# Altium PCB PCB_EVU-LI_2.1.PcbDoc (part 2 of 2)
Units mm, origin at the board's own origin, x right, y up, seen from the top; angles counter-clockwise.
Board outline 33.02 x 17.78 mm, 4 copper layers (Top, Int_1, Int_2, Bot), stack 1.546 mm thick; 75 components, 60 nets, 297 pads, 132 vias.
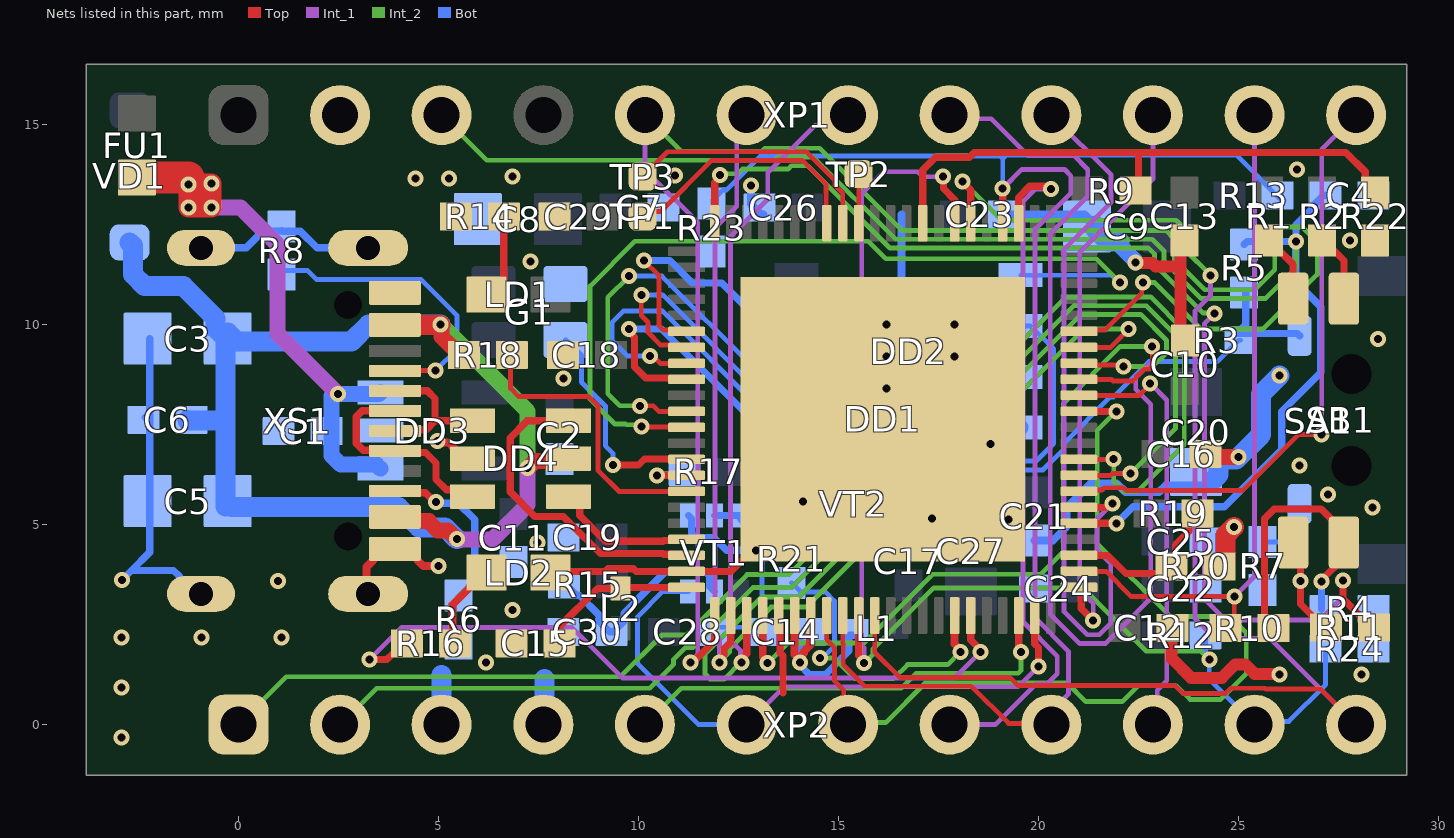
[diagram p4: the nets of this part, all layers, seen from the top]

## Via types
v1: diameter 0.4, hole 0.2, Top to Bot, 132 vias

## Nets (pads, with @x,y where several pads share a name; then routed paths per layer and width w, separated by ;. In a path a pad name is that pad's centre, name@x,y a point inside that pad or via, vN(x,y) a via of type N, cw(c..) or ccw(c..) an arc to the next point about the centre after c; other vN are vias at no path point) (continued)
+5V_USB_IN: C3.2 C5.2 C6.2 DD4.5 R18.1 VD1.A XS1.A4_B9 XS1.B4_A9 | length 33.7
  Top w0.3: v1@5.045,9.995 v1(5.055,10.005) v1@5.072,9.988 ; R18.1@5.331,9.444 5.372,9.403 5.472,9.403 R18.1@5.631,9.244
  Top w0.4: XS1.B4_A9@3.91,5.195 4.01,5.095 4.767,5.095 4.767,5.066 4.983,4.851 5.242,4.851 v1(5.457,4.636) ; v1@5.072,9.988 5.072,9.703 R18.1@5.331,9.444 ; v1(7.228,6.411) 7.406,6.589 8.189,6.589 DD4.5@8.25,6.65
  Top w0.5: XS1.A4_B9@3.91,9.995 v1@5.045,9.995
  Int_1 w0.4: v1(5.457,4.636) 5.463,4.63 6.36,4.63 7.228,5.498 v1(7.228,6.411)
  Int_2 w0.4: v1(5.055,10.005) 7.228,7.832 v1(7.228,6.411)
  Bot w0.4: C5.2@-0.32,5.588 C5.2@-0.171,5.439 ; C3.2@-0.32,9.652 -0.32,9.739 C3.2@-0.262,9.798
  Bot w0.5: VD1.A@-2.72,12.055 -2.641,11.976 -2.641,11.256 -2.348,10.963 -1.378,10.963 -0.57,10.155 -0.57,9.902 -0.32,9.652 -0.32,7.605 ; C6.2@-1.278,7.62 -1.263,7.605 -0.32,7.605 ; C5.2@-0.32,5.455 -0.32,5.588 -0.32,7.605 ; C3.2@-0.262,9.798 -0.037,9.573 2.818,9.573 3.25,10.005 v1(5.055,10.005) ; C5.2@-0.171,5.439 3.967,5.439 ; 3.999,5.442 4.51,4.931 5.162,4.931 v1(5.457,4.636)
+V_IN: C1.2 DD3.1 DD3.3 FU1.2 | length 24.3
  Top w0.5: v1(-1.245,13.505) v1(-1.245,12.93) ; v1@-1.22,13.53 v1(-0.67,13.53) v1@-0.67,13.505 ; v1(-1.245,12.93) v1@-0.67,13.505 ; v1(-1.245,12.93) v1(-0.67,12.93) v1@-0.67,13.505
  Top w0.8: FU1.2@-2.54,13.678 v1@-1.245,13.678
  Int_1 w0.4: v1(2.485,8.269) 0.978,9.776 0.978,11.996 0.044,12.93 v1(-0.67,12.93) ; v1(-1.245,12.93) v1@-0.67,13.505 ; v1(-1.245,12.93) v1(-0.67,12.93) ; v1(-1.245,12.93) v1(-1.245,13.505) -0.695,13.505 v1(-0.67,13.53) v1@-0.67,13.505 ; v1(-0.67,12.93) v1@-0.67,13.505
  Int_2 w0.4: v1(-1.245,12.93) v1(-1.245,13.505) -0.695,13.505 v1(-0.67,13.53) v1@-0.67,13.505 ; v1(-1.245,12.93) v1(-0.67,12.93) v1@-0.67,13.505 ; v1(-1.245,12.93) v1@-0.67,13.505
  Bot w0.4: v1@-1.232,13.492 -1.195,13.53 v1(-0.67,13.53) ; v1@-0.67,13.538 v1(-0.67,13.53) ; DD3.1@3.547,6.399 3.447,6.499 2.557,6.499 2.323,6.734 2.323,8.221 2.372,8.269 v1(2.485,8.269) 3.517,8.269 DD3.3@3.547,8.299 ; v1(-0.67,12.93) v1(-1.245,13.505) v1(-1.245,12.93) v1(-0.67,12.93) ; v1(-0.67,12.93) v1(-0.67,13.53)
CLK_25MHz: DD1.14 G1.3 | length 5.5
  Top w0.18: v1(9.361,6.49) 9.997,6.49 10.149,6.642 11.143,6.642 DD1.14@11.155,6.63
  Bot w0.12: G1.3@8.174,9.616 8.186,9.616 8.574,9.228 8.574,8.565 9.173,7.966 9.173,6.972 9.359,6.786 9.359,6.491 v1(9.361,6.49)
GND: C1.1 C2.1 C3.1 C4.1 C5.1 C6.1 C7.1 C8.1 C9.1 C10.1 C11.1 C12.1 C13.1 C14.1 C15.1 C16.1 C17.1 C18.1 C19.1 C20.1 C21.1 C22.1 C23.1 C24.1 C25.1 C26.1 C27.1 C28.1 C29.1 C30.2 DD1.21 DD1.27 DD1.89 DD2.4 DD2.EP DD3.2 DD4.2 G1.2 LD2.2 R4.1 R6.2 R7.1 R8.2 R14.2 R20.2 R22.1 R23.1 R24.1 SB1.1 VT1.1 VT2.2 XP1.2 XP2.3 XP2.4 XS1.A1_B12 XS1.B1_A12 XS1.S1 XS1.S2 XS1.S3 XS1.S4 | length 65.3
  Top w0.18: LD2.2@7.975,3.806 7.999,3.83 9.169,3.83 9.234,3.895 9.876,3.895 9.941,3.83 DD1.21@11.2,3.83 12.305,3.83 DD1.89@12.818,4.343 ; DD1.89@12.965,4.427 v1(14.113,5.575) ; DD1.27@13.505,2.68 13.535,2.65 13.535,1.795 13.615,1.715 13.615,0.79
  Top w0.2: XS1.S3@3.24,3.27 3.199,3.311 3.199,3.943 3.36,4.104 3.36,4.195 3.56,4.395 XS1.B1_A12@3.91,4.395 4.26,4.395 4.46,4.195 4.46,4.122 4.621,3.962 v1(5,3.962) v1@5.023,3.962 ; v1(4.974,7.096) 5.012,7.058 5.243,7.058 5.4,6.9 5.4,6.845 5.6,6.645 DD4.2@5.9,6.645
  Top w0.3: v1(22.42,11.554) 22.44,11.535 22.849,11.535 22.928,11.456 23.555,11.456 ; C12.1@23.33,2.33 23.33,1.655 23.813,1.172 24.584,1.172 24.917,1.505 25.165,1.505 25.401,1.269 26.008,1.269 v1(26.028,1.25) ; C10.1@23.555,9.645 23.555,11.405 C13.1@23.555,12.105
  Top w0.4: XP2.4@7.493,0.127 XP2.4@7.62,0 ; C16.1@24.198,6.764 24.276,6.686 v1(25.001,6.686)
  Top w0.5: R20.2@24.58,3.955 24.68,4.055 24.68,4.738 v1(24.886,4.944)
  Int_1 w0.5: XP2.4@7.62,0 XP2.4@7.622,0.002
  Bot w0.12: C28.1@11.842,2.427 11.849,2.434 13.083,2.434 13.09,2.44 13.09,4.133 12.94,4.283 v1(12.94,4.358)
  Bot w0.18: v1(-2.917,3.614) -2.676,3.855 ; C6.1@-2.336,7.678 C6.1@-2.278,7.62 ; C3.1@-2.22,9.652 -2.22,4.311 -2.676,3.855 ; XS1.S4@-0.94,3.27 -1.145,3.27 -1.478,3.603 -1.478,3.709 -1.624,3.855 -2.676,3.855 ; XS1.S2@-0.94,11.92 0.191,11.92 0.615,12.344 1.069,12.344 1.08,12.355 1.099,12.336 1.545,12.336 1.961,11.92 XS1.S1@3.24,11.92 ; XP2.3@5.08,0 XP2.3@5.08,0.34 ; VT1.1@11.247,5.23 11.327,5.15 11.327,4.779 11.433,4.673 11.883,4.673 12.198,4.358 v1(12.94,4.358) ; v1(14.113,5.575) 14.113,5.634 14.21,5.731 14.21,5.913 14.315,6.019 VT2.2@14.718,6.019
  Bot w0.2: v1(12.818,13.476) 12.818,13.005 13.068,12.755 C26.1@13.13,12.755 ; 16.58,12.755 16.58,9.505 DD2.EP@16.755,9.33 ; C23.1@19.005,12.755 21.155,12.755 C9.1@21.43,12.48 ; C21.1@19.894,4.609 20.367,4.609 20.705,4.947 20.705,5.43 21.305,6.03 21.955,6.03 22.172,5.813 23.013,5.813 23.18,5.98 C20.1@24.355,5.98
  Bot w0.3: C20.1@24.355,5.98 C20.1@24.379,5.98
  Bot w0.4: v1(18.793,7.021) 18.901,7.021 19.305,7.425 DD2.4@19.555,7.425 ; 22.027,12.08 22.027,11.986 22.42,11.593 v1(22.42,11.554)
  Bot w0.5: XP2.3@5.08,0.34 5.08,1.237 ; XP2.4@7.62,0 7.643,0.023 7.643,1.145 ; C17.1@16.846,4.876 17.116,5.146 18.125,5.146 C27.1@18.311,5.332 18.512,5.131 v1(19.254,5.131) ; C9.1@21.43,12.48 21.43,12.38 21.73,12.08 22.027,12.08 ; C20.1@24.379,6.129 24.5,6.25 24.5,6.538 24.589,6.627 24.943,6.627 25.566,7.25 25.566,8.266 v1(26.03,8.73)
  other v1: -2.92,-0.32 -2.92,0.93 28.08,1.247 6.19,1.557 -2.92,2.18 -0.92,2.18 1.08,2.18 6.85,2.87 0.984,3.596 7.472,4.554 17.339,5.151 28.348,5.427 27.237,5.754 26.53,6.48 16.2,8.4 8.12,8.651 16.2,9.2 17.9,9.2 28.487,9.635 16.2,10 17.9,10 7.304,11.573 27.783,12.105 4.43,13.654 5.258,13.653 6.848,13.704 10.915,13.732 26.465,13.875
M0: R4.2 R10.1 SA1.11 | length 7.8
  Top w0.18: R10.1@26.183,2.153 25.981,2.355 25.855,2.355 25.648,2.562 25.648,5.148 25.892,5.392 27.065,5.392 27.635,4.822 SA1.11@27.635,4.552 27.635,4.175 27.076,3.616 v1(27.076,3.582)
  Bot w0.18: R4.2@27.076,2.876 v1(27.076,3.582)
M1: R7.2 R11.1 SA1.22 | length 4.1
  Top w0.18: SA1.22@26.365,4.552 26.546,4.371 v1(26.546,3.586) 26.546,3.015 27.139,2.422 R11.1@27.189,2.422
  Bot w0.12: R7.2@25.669,4.565 26.019,4.565 26.546,4.038 v1(26.546,3.586)
  Bot w0.18: v1@26.52,3.586 v1(26.546,3.586)
MCU_ADC0/PA0: DD1.23 DD1.61 XP1.5 | length 44.4
  Top w0.12: v1(11.304,1.548) v1@11.352,1.548 ; DD1.23@11.898,2.673 DD1.23@11.905,2.68 ; DD1.61@21.055,9.83 21.088,9.863 21.66,9.863 22.581,10.784 22.581,11.027 v1(22.608,11.054)
  Top w0.18: v1@11.352,1.548 11.898,2.094 DD1.23@11.898,2.673
  Int_1 w0.12: XP1.5@10.16,15.24 10.16,13.875 11.48,12.555 11.48,1.758 11.304,1.582 v1(11.304,1.548)
  Int_2 w0.12: XP1.5@10.16,15.24 11.07,14.33 13.077,14.33 13.156,14.41 14.526,14.41 16.582,12.354 23.176,12.354 23.399,12.131 23.399,11.627 24.157,10.87 25.401,10.87 25.908,11.377 25.908,12.243 26.105,12.441 26.588,12.441 26.972,12.056 26.972,11.256 25.603,9.887 24.066,9.887 22.902,11.051 22.611,11.051 v1(22.608,11.054)
MCU_ADC1/PA1: DD1.24 DD1.60 XP1.6 | length 30.5
  Top w0.12: DD1.60@21.055,9.43 21.806,9.43 22.246,9.87 v1(22.246,9.894)
  Top w0.18: v1(12.024,1.548) 12.024,1.624 12.14,1.74 12.14,1.896 12.305,2.061 DD1.24@12.305,2.68
  Int_1 w0.12: v1@12.024,1.533 12.024,2.118 11.908,2.233 11.908,12.406 12.458,12.956 12.458,14.998 XP1.6@12.7,15.24
  Int_2 w0.12: v1@12.024,1.533 12.024,1.564 12.277,1.817 12.277,1.902 13.315,2.94 14.187,2.94 21.141,9.894 v1(22.246,9.894)
MCU_ADC2/PA2: DD1.25 DD1.59 XP1.7 | length 36.1
  Top w0.12: v1@12.58,1.58 v1@12.58,1.64 ; DD1.59@21.055,9.03 21.093,8.992 22.092,8.992 v1(22.13,8.954)
  Top w0.18: v1@12.58,1.64 12.705,1.765 DD1.25@12.705,2.68
  Int_1 w0.12: v1@12.58,1.58 12.552,1.608 12.552,1.85 12.298,2.104 12.298,12.201 13.23,13.133 13.23,13.792 14.42,14.983 14.983,14.983 XP1.7@15.24,15.24
  Int_2 w0.12: v1@12.58,1.58 12.14,1.14 11.79,1.14 11.664,1.266 11.664,1.773 13.082,3.191 14.006,3.191 21.069,10.254 22.552,10.254 23.202,9.603 23.202,9.297 22.86,8.954 v1(22.13,8.954)
  other v1: 12.58,1.548
MCU_ADC3/PA3: DD1.26 DD1.58 XP1.8 | length 44.2
  Top w0.12: DD1.58@21.055,8.63 21.827,8.63 21.862,8.594 22.361,8.594 22.431,8.664 22.431,8.679 22.642,8.89 22.772,8.89 22.842,8.96 v1@22.842,9.454
  Top w0.18: DD1.26@13.105,2.725 13.105,1.687 13.225,1.567 v1(13.225,1.543)
  Int_1 w0.12: XP1.8@17.78,15.24 17.875,15.145 18.815,15.145 19.73,14.23 20.879,14.23 21.231,13.878 21.231,13.206 20.295,12.27 20.295,2.765 21.034,2.026 21.673,2.026 22.805,3.158 22.805,8.007 22.431,8.38 22.431,8.679 22.842,9.09 v1(22.842,9.454)
  Int_2 w0.12: v1(13.225,1.543) 13.244,1.543 13.745,2.044 15.643,2.044 17.357,3.758 20.054,3.758 20.625,4.329 20.625,8.032 22.047,9.454 v1(22.842,9.454)
MCU_ADC4/PA5: DD1.30 DD1.56 XP2.7 | length 24.2
  Top w0.12: DD1.30@14.705,2.725 14.705,2.122 14.898,1.929 14.898,1.092 15.13,0.86 15.13,0.11 XP2.7@15.24,0
  Top w0.18: DD1.56@21.055,7.83 21.056,7.831 v1(21.946,7.832) v1(21.946,7.832)
  Int_2 w0.12: XP2.7@15.24,0 15.29,0.05 16.175,0.05 17.166,1.041 20.719,1.041 21.184,0.576 22.093,0.576 22.504,0.987 23.431,0.987 23.787,0.63 24.555,0.63 25.195,1.27 25.195,2.299 24.789,2.705 23.287,2.705 21.468,4.525 21.468,7.354 v1(21.946,7.832)
MCU_ADC5/PC8_DBG: DD1.31 DD1.70 R13.1 R23.2 XP2.9 | length 40.6
  Top w0.12: DD1.31@15.105,2.68 15.105,2.033 15.119,2.018 15.119,1.499 15.661,0.958 18.323,0.958 19.252,0.03 20.29,0.03 XP2.9@20.32,0
  Top w0.18: v1(19.104,13.404) 19.105,13.402 DD1.70@19.105,12.535
  Int_1 w0.12: v1(19.104,13.404) 19.58,13.88 20.649,13.88 20.807,13.721 20.807,13.282 19.915,12.39 19.915,2.67 20.748,1.837 20.748,0.76 20.32,0.332 XP2.9@20.32,0
  Bot w0.12: R23.2@11.86,13.028 11.86,13.112 12.115,13.368 12.2,13.368 13.05,14.218 19.033,14.218 19.104,14.148 ; v1(19.104,13.404) 19.104,14.148 ; XP2.9@20.32,0 XP2.9@20.326,0.006 ; R13.1@26.133,13.1 26.083,13.1 24.95,14.233 19.189,14.233 19.104,14.148
MCU_ADC6/PC6: DD1.32 DD1.73 R12.2 R24.2 XP2.11 | length 32.6
  Top w0.18: DD1.32@15.505,2.68 15.505,1.727 15.638,1.594 v1(15.638,1.535) ; v1(17.617,13.699) 17.624,13.693 17.624,13.4 17.905,13.119 DD1.73@17.905,12.58
  Int_1 w0.12: v1(15.638,1.535) 15.638,1.917 15.58,1.975 15.58,13.278 16.125,13.824 16.976,13.824 17.101,13.699 v1(17.617,13.699)
  Int_2 w0.12: v1(15.638,1.535) 15.856,1.753 15.856,1.888 17.385,3.417 21.106,3.417 22.687,1.835 24.059,1.835 24.267,1.627 v1(24.269,1.627)
  Bot w0.12: R12.2@24.173,2.235 24.173,1.799 24.269,1.703 v1(24.269,1.627) 24.269,1.131 XP2.11@25.4,0 25.481,0.081 26.26,0.081 27.177,0.998 R24.2@27.177,1.9
MCU_ADC7/PC7: DD1.33 DD1.72 XP2.12 | length 36.2
  Top w0.12: DD1.33@15.905,2.68 15.905,1.803 16.528,1.18 19.28,1.18 19.48,0.98 23.405,0.98 23.605,0.78 24.679,0.78 24.809,0.91 25.659,0.91 25.679,0.89 27.05,0.89 XP2.12@27.94,0
  Top w0.18: v1(18.104,13.583) 18.104,13.569 18.305,13.368 DD1.72@18.305,12.58
  Int_1 w0.12: v1(24.301,11.235) 24.301,10.729 23.915,10.343 23.915,2.645 24.405,2.155 25.785,2.155 XP2.12@27.94,0
  Int_2 w0.12: v1(18.104,13.583) 19.077,12.61 23.439,12.61 23.674,12.375 23.674,11.862 v1(24.301,11.235)
  other v1: 24.301,11.235 24.301,11.235 24.301,11.235 18.104,13.583 18.104,13.583 18.104,13.583
MCU_nRST: C4.2 DD1.49 R5.2 XP1.3 | length 38.9
  Top w0.18: DD1.49@21.055,5.03 21.057,5.032 21.947,5.032 v1(21.95,5.034)
  Int_2 w0.12: XP1.3@5.08,15.24 6.21,14.11 13.42,14.11 13.499,14.19 14.37,14.19 16.426,12.134 22.842,12.134 23.139,11.838 23.139,11.577 24.066,10.65 25.673,10.65 26.439,11.415 v1(26.439,12.081)
  Bot w0.18: v1(21.95,5.034) 22.361,5.446 24.648,5.446 26.078,6.876 26.078,7.828 27.055,8.805 27.055,10.445 26.431,11.069 26.431,12.028 26.439,12.035 v1(26.439,12.081) ; R5.2@25.142,12.007 25.216,12.081 v1(26.439,12.081) ; C4.2@27.177,13.234 27.127,13.234 26.867,12.974 26.867,12.924 26.439,12.496 v1(26.439,12.081)
MCU_PA4: DD1.57 XP2.10 | length 10.7
  Top w0.12: DD1.57@21.055,8.23 22.521,8.23 22.791,8.5 v1(22.791,8.53)
  Int_1 w0.12: v1(22.791,8.53) 23.205,8.116 23.205,1.095 22.97,0.86 22.97,0.11 XP2.10@22.86,0
  other v1: 22.791,8.53 22.791,8.53 22.791,8.53
MCU_PA6: DD1.53 XP2.1 | length 35.1
  Top w0.12: DD1.53@21.01,6.63 21.87,6.63 v1(21.88,6.64)
  Int_2 w0.12: XP2.1@0,0 1.197,1.197 9.544,1.197 10.588,2.241 11.204,2.241 12.714,3.751 13.755,3.751 20.699,10.694 22.8,10.694 23.642,9.852 23.642,6.997 22.475,5.83 22.13,5.83 21.88,6.08 v1(21.88,6.64)
MCU_PA7: DD1.52 XP2.2 | length 30.8
  Top w0.12: DD1.52@21.01,6.23 21.802,6.23 21.852,6.28 v1@22.305,6.28
  Int_2 w0.12: XP2.2@2.54,0 3.45,0.91 10.275,0.91 10.877,1.512 10.877,1.63 11.172,1.925 11.358,1.925 12.862,3.429 13.479,3.429 13.83,3.429 20.875,10.474 22.696,10.474 23.422,9.747 23.422,7.397 v1@22.305,6.28
  other v1: 22.3,6.28
MCU_PA8: DD1.51 XP1.12 | length 15
  Top w0.12: DD1.51@21.055,5.83 21.09,5.865 21.59,5.865 21.645,5.92 22.113,5.92 22.178,5.855 25.105,5.855 26.505,7.255 v1(27.08,7.255)
  Int_1 w0.12: v1(27.08,7.255) 27.08,14.38 XP1.12@27.94,15.24
  other v1: 27.08,7.255 27.08,7.255 27.08,7.255
MCU_PA9: DD1.50 XP1.9 | length 19.2
  Top w0.18: DD1.50@21.055,5.43 21.695,5.43 21.795,5.53 v1(21.855,5.53)
  Int_1 w0.12: XP1.9@20.32,15.24 21.815,13.745 21.815,13.062 20.638,11.885 20.638,2.826 21.218,2.246 21.521,2.246 21.806,2.531 21.806,4.029 21.46,4.375 21.46,5.135 v1(21.855,5.53)
MCU_PA10: DD1.46 R10.2 XP1.11 | length 17.3
  Top w0.12: DD1.46@21.055,3.83 21.09,3.795 21.375,3.795 21.41,3.83 21.69,3.83 22.318,3.202 v1(24.895,3.202) 24.895,2.495 R10.2@24.755,2.355
  Int_1 w0.12: v1(24.895,3.202) 25.4,3.708 XP1.11@25.4,15.24
MCU_PA11: DD1.45 XP1.10 | length 14.5
  Top w0.18: DD1.45@21.055,3.43 21.055,3.415 21.07,3.4 21.07,2.903 v1(21.367,2.606)
  Int_1 w0.12: v1(21.367,2.606) 21.367,3.034 21.03,3.371 21.03,11.805 22.86,13.635 XP1.10@22.86,15.24
  other v1: 21.367,2.606 21.367,2.606 21.367,2.606
MCU_PA12: DD1.43 VT1.6 XP2.6 | length 15.2
  Top w0.18: DD1.43@19.905,2.68 19.905,2.02 20,1.925 20,1.46 v1(20.005,1.455)
  Int_1 w0.12: XP2.6@12.7,0 13.645,0.945 19.495,0.945 v1(20.005,1.455)
  Bot w0.12: VT1.6@11.247,3.33 10.61,3.33 9.976,2.696 9.976,1.525 11.501,0 XP2.6@12.7,0
MCU_PA13: DD1.42 XP2.5 | length 11.3
  Top w0.18: DD1.42@19.505,2.68 19.505,1.928 19.561,1.872 v1(19.561,1.813)
  Int_2 w0.12: XP2.5@10.16,0 11.07,0.91 16.568,0.91 16.94,1.282 19.49,1.282 19.561,1.353 v1(19.561,1.813)
MCU_PA15: DD1.39 R16.2 | length 18.4
  Top w0.18: v1(3.28,1.63) 3.708,1.63 3.847,1.769 3.897,1.769 4.107,1.979 R16.2@4.107,2.029 ; DD1.39@18.305,2.68 18.305,2.119 18.544,1.88 v1(18.544,1.82)
  Int_1 w0.12: v1(3.28,1.63) 4.079,2.429 8.329,2.429 9.591,1.168 17.901,1.168 18.544,1.811 v1(18.544,1.82)
MCU_PB0: DD1.12 DD2.1 | length 22.2
  Top w0.12: v1(10.078,7.452) 10.09,7.441 11.144,7.441 DD1.12@11.155,7.43
  Int_2 w0.12: v1(10.078,7.452) 10.033,7.498 9.698,7.498 9.682,7.514 9.412,7.514 8.789,8.137 8.789,10.963 9.91,12.084 15.742,12.084 16.18,11.646 21.444,11.646 v1(22.036,11.054)
  Bot w0.12: DD2.1@19.555,11.235 21.826,11.235 22.006,11.054 v1(22.036,11.054)
MCU_PB1: DD1.11 DD2.6 | length 10.5
  Top w0.12: v1(10.033,7.971) 10.367,7.971 10.508,7.83 DD1.11@11.155,7.83
  Int_2 w0.12: v1(9.763,11.215) 9.23,10.682 9.23,8.274 9.534,7.971 v1(10.033,7.971)
  Bot w0.12: v1(9.763,11.215) 10.583,11.215 12.863,8.935 13.715,8.935 DD2.6@13.955,8.695
MCU_PB2: DD1.9 DD2.5 | length 7.6
  Top w0.18: v1(9.756,9.888) 9.756,9.828 9.899,9.685 9.899,8.947 10.181,8.665 11.12,8.665 DD1.9@11.155,8.63
  Bot w0.12: DD2.5@13.927,7.453 DD2.5@13.955,7.425
  Bot w0.18: v1(9.756,9.888) 10.574,9.888 13.009,7.453 DD2.5@13.927,7.453
MCU_PB3: DD1.8 DD2.2 | length 18.9
  Top w0.12: v1(10.289,9.213) 10.365,9.213 10.548,9.03 DD1.8@11.155,9.03
  Bot w0.12: v1(10.289,9.213) 9.726,9.213 9.342,9.597 9.342,10.058 9.627,10.342 10.596,10.342 13.021,7.916 14.611,7.916 14.73,7.797 14.73,7.589 15.73,6.589 19.937,6.589 20.375,7.028 20.375,9.395 19.805,9.965 DD2.2@19.555,9.965
MCU_PB4: DD1.7 DD2.3 | length 14.2
  Top w0.12: v1(10.07,10.744) 10.07,10.228 10.237,10.062 10.237,9.805 10.551,9.49 11.095,9.49 DD1.7@11.155,9.43
  Bot w0.12: v1(10.07,10.744) 10.604,10.744 13.184,8.164 14.733,8.164 14.977,7.92 14.977,7.782 15.804,6.954 18.072,6.954 18.602,7.484 18.602,7.967 19.065,8.43 19.065,8.455 19.305,8.695 DD2.3@19.555,8.695
MCU_PB5: DD1.6 DD2.7 | length 7
  Top w0.12: v1(10.136,11.6) 10.515,11.221 10.515,9.973 10.623,9.865 11.12,9.865 DD1.6@11.155,9.83
  Bot w0.18: v1(10.136,11.6) 10.784,11.6 11.343,11.041 12.079,11.041 13.155,9.965 DD2.7@13.955,9.965
MCU_PB10: DD1.88 R11.2 | length 28.4
  Top w0.12: R11.2@28.28,2.43 R11.2@28.28,2.482
  Top w0.18: DD1.88@11.905,12.58 11.905,13.552 12.037,13.684 v1(12.037,13.744) ; v1(27.614,3.602) 27.614,3.148 R11.2@28.28,2.482
  Int_1 w0.12: v1(24.405,10.279) 24.148,10.022 24.148,3.152 24.686,2.613 27.036,2.613 27.614,3.191 v1(27.614,3.602)
  Int_2 w0.12: v1(12.037,13.744) 12.066,13.773 12.477,13.773 12.594,13.89 13.741,13.89 13.821,13.97 14.232,13.97 16.287,11.914 22.751,11.914 22.899,11.767 22.899,11.506 24.116,10.288 24.377,10.288 v1@24.431,10.234
MCU_PC4: DD1.75 R9.2 R22.2 | length 14.4
  Top w0.18: DD1.75@17.105,12.535 17.105,13.863 17.426,14.184 18.276,14.184 18.393,14.3 20.322,14.3 22.502,14.3 ; R9.2@22.423,13.35 22.502,13.429 22.502,14.3 ; R22.2@28.412,13.305 28.166,13.551 28.166,13.821 27.688,14.3 22.502,14.3
MCU_PC9: DD1.69 XP2.8 | length 17.8
  Top w0.18: DD1.69@19.505,12.58 19.505,13.18 19.783,13.458 20.241,13.458 v1(20.313,13.387)
  Int_1 w0.12: XP2.8@17.78,0 18.92,0 19.944,1.024 20.218,1.024 20.467,1.274 20.467,1.712 19.614,2.566 19.614,13.089 19.912,13.387 v1(20.313,13.387)
  other v1: 20.313,13.387 20.313,13.387 20.313,13.387
NetC14_2: C14.2 DD1.28 DD1.29 L1.2 | length 5.5
  Top w0.2: DD1.28@13.905,2.725 13.905,1.752 v1@13.98,1.677 ; v1(14.034,1.548) 14.034,1.692 14.134,1.793 14.134,1.832 14.285,1.983 14.285,2.705 DD1.29@14.305,2.725
  Bot w0.18: v1(14.034,1.548) 14.034,1.488 14.268,1.254 14.673,1.254 15.258,1.838 15.258,2.213 15.278,2.234 L1.2@15.456,2.234 ; v1@14.034,1.622 14.034,2.184 C14.2@14.29,2.44
NetC15_2: C15.2 DD1.22 L2.2 | length 4.1
  Top w0.18: C15.2@8.02,1.98 8.02,2.445 8.98,3.405 L2.2@9.555,3.405 9.58,3.43 DD1.22@11.2,3.43
NetC30_1: C30.1 R15.2 VT1.5 | length 5.4
  Bot w0.18: R15.2@8.189,3.5 8.449,3.24 8.511,3.24 9.017,2.735 9.017,2.58 9.277,2.32 9.377,2.32 9.637,2.58 9.637,2.789 9.929,3.082 ; 9.929,3.082 10.667,3.82 11.671,3.82 11.777,3.715 11.777,3.45 VT1.5@11.897,3.33
NetDD1_15: DD1.15 R17.2 | length 1.4
  Top w0.18: v1(10.46,6.234) 10.462,6.232 11.153,6.232 DD1.15@11.155,6.23
  Bot w0.18: v1(10.46,6.234) 11.066,6.234 R17.2@11.15,6.318
NetDD1_16: DD1.16 R18.2 | length 7.2
  Top w0.12: R18.2@6.8,9.244 6.8,8.406 7.004,8.202 8.752,8.202 8.989,7.965 8.989,6.353 9.511,5.83 DD1.16@11.155,5.83
NetDD1_47: DD1.47 R19.1 R20.1 | length 4.2
  Top w0.18: DD1.47@21.055,4.23 21.733,4.23 22.188,3.775 23.25,3.775 23.43,3.955 23.43,4.505 23.765,4.84 23.765,5.24 R19.1@23.83,5.305
NetDD1_79: DD1.79 TP2.1 | length 1.2
  Top w0.12: DD1.79@15.503,12.537 TP2.1@15.503,13.761
  Top w0.3: TP2.1@15.501,13.763 TP2.1@15.503,13.761
NetDD1_80: DD1.80 TP3.1 | length 6.5
  Top w0.12: TP3.1@10.1,13.7 10.724,14.324 14.188,14.324 14.908,13.605 14.908,13.48 15.105,13.283 DD1.80@15.105,12.58
NetDD1_81: DD1.81 TP1.1 | length 6.4
  Top w0.12: TP1.1@10.1,12.7 10.228,12.828 10.56,12.828 11.835,14.104 14.097,14.104 14.688,13.514 14.688,12.597 DD1.81@14.705,12.58
NetLD1_2: LD1.2 R14.1 | length 2.2
  Top w0.18: LD1.2@6.2,10.75 6.242,10.75 6.632,11.14 R14.1@6.632,12.7
NetLD2_1: LD2.1 R16.1 | length 2.2
  Top w0.12: LD2.1@6.15,3.8 LD2.1@6.2,3.8
  Top w0.2: R16.1@5.349,2.029 5.349,2.999 LD2.1@6.15,3.8
NetR1_2: R1.2 SA1.2 | length 2
  Top w0.12: SA1.2@26.365,10.648 SA1.2@26.365,10.918
  Top w0.18: R1.2@25.767,12.105 25.767,12.055 26.027,11.795 26.077,11.795 26.365,11.507 26.365,10.918 SA1.2@26.365,10.648
NetR2_2: R2.2 SA1.1 | length 1.8
  Top w0.18: R2.2@27.089,12.15 27.089,12.1 27.349,11.84 27.399,11.84 27.635,11.604 SA1.1@27.635,10.648
NetR3_1: R3.1 R5.1 SB1.2 VT2.3 | length 13.5
  Bot w0.12: VT2.3@16.018,5.519 16.118,5.619 16.383,5.619 17.134,6.369 20.112,6.369 20.631,6.889 20.631,7.027 21.796,8.192 21.877,8.192 22.76,9.076 24.469,9.076 25.003,9.61 R3.1@25.053,9.61
  Bot w0.18: R5.1@25.18,10.807 25.18,10.005 24.955,9.78 26.468,9.78 SB1.2@26.528,9.72
NetR6_1: R6.1 XS1.B5 | length 4.4
  Top w0.18: XS1.B5@3.91,5.845 3.956,5.799 4.673,5.799 4.906,5.566 v1(4.935,5.566)
  Bot w0.18: v1(4.935,5.566) 4.966,5.536 5.495,5.536 5.906,5.125 5.906,3.581 R6.1@5.505,3.18
NetR8_1: R8.1 XS1.A5 | length 7.5
  Top w0.12: XS1.A5@3.91,8.845 3.92,8.855 v1(4.93,8.855)
  Bot w0.12: R8.1@1.08,11.355 1.724,11.355 1.951,11.127 4.563,11.127 5.465,10.225 5.465,9.39 v1(4.93,8.855)
TST: DD1.38 R21.1 | length 7.9
  Top w0.2: DD1.38@17.925,2.745 DD1.38@17.905,2.725 17.905,2.014 18.044,1.874 v1(18.044,1.82)
  Int_2 w0.12: v1(14.534,1.667) 14.885,1.667 15.395,1.156 16.38,1.156 16.726,1.502 17.727,1.502 v1(18.044,1.82)
  Bot w0.12: R21.1@13.825,3.546 14.053,3.319 14.664,3.319 14.896,3.087 14.896,1.961 14.602,1.667 v1(14.534,1.667)
TT: R21.2 VT1.2 VT1.3 VT2.1 | length 3.2
  Bot w0.12: R21.2@13.825,4.746 13.958,4.879 14.578,4.879 VT2.1@14.718,5.019
  Bot w0.18: VT1.2@11.897,5.23 VT1.3@12.547,5.23 12.547,5.14 12.667,5.02 12.746,5.02 12.772,4.994 13.577,4.994 R21.2@13.825,4.746
USB_D_n: DD4.1 XS1.A7 XS1.B7 | length 3.7
  Top w0.18: XS1.A7@3.91,7.345 3.938,7.373 4.69,7.373 4.912,7.595 ; XS1.B7@3.91,8.345 4.72,8.345 4.912,8.153 4.912,7.595 ; DD4.1@5.9,7.595 4.912,7.595
USB_D_p: DD4.3 XS1.A6 XS1.B6 | length 5.4
  Top w0.18: XS1.A6@3.91,7.845 3.093,7.845 2.944,7.696 2.944,7.035 3.118,6.861 3.894,6.861 3.952,6.803 4.677,6.803 4.938,6.542 4.938,6.128 5.197,5.87 5.425,5.87 5.725,5.87 DD4.3@5.9,5.695
USB_n: DD1.20 DD4.6 | length 8
  Top w0.18: DD4.6@8.2,7.595 7.219,7.595 6.791,7.167 6.791,5.82 7.406,5.205 8.117,5.205 8.291,5.031 9.047,4.275 10.611,4.275 10.626,4.26 11.125,4.26 DD1.20@11.155,4.23
USB_p: DD1.19 DD4.4 | length 3.5
  Top w0.18: DD4.4@8.32,5.695 8.53,5.485 8.53,5.23 9.176,4.585 10.611,4.585 10.626,4.6 11.125,4.6 DD1.19@11.155,4.63
pads on no net: DD1.2 DD1.3 DD1.4 DD1.5 DD1.35 DD1.41 DD1.62 DD1.63 DD1.64 DD1.65 DD1.67 DD1.68 DD1.74 DD1.76 DD1.78 DD1.83 DD1.84 DD1.85 DD1.86 DD1.87 DD3.4 G1.1 SB1.10 SB1.mnt XS1. XS1.A8 XS1.B8

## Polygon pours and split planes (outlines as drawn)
GND on Int_1 "Int_1-GND" (solid, pour order 12): -3.81,-1.27 29.21,-1.27 29.21,16.51 -3.81,16.51
GND on Int_2 "Int_2-GND" (solid, pour order 14): -3.81,-1.27 29.21,-1.27 29.21,16.51 -3.81,16.51
GND on Bot "Bot-GND" (solid, pour order 9): -3.81,-1.27 29.21,-1.27 29.21,16.51 -3.81,16.51
GND on Top "Top-GND" (solid, pour order 10): -3.81,-1.27 29.21,-1.27 29.21,16.51 -3.81,16.51

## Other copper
Top:
  pour cut-out: 8.173,13.189 8.818,13.189 8.818,12.211 8.173,12.211
  pour cut-out: 5.705,13.189 6.35,13.189 6.35,12.211 5.705,12.211
  pour cut-out: 6.677,11.404 7.323,11.404 7.323,10.095 6.677,10.095
  pour cut-out: 9.103,4.057 10.603,4.057 10.74,3.92 10.618,3.798 10.618,3.695 9.103,3.695
  pour cut-out: 27.439,13.688 27.451,13.7 28.068,13.7 28.068,13.388 28.802,12.654 28.757,12.609 28.757,12.5 27.433,12.5
  pour cut-out: 23.713,4.305 24.134,4.727 24.353,4.727 24.353,3.343 24.314,3.304 23.745,3.304
  pour cut-out: 23.38,7.114 24.198,7.114 24.198,6.117 23.53,6.117 23.398,6.432
  pour cut-out: 11.755,12.005 20.505,12.005 20.505,3.205 11.705,3.205 11.705,4.855
  pour cut-out: 27.204,8.562 28.842,8.562 28.842,6.456 27.197,6.456 27.197,8.574
  pour cut-out: 3.49,-0.858 3.49,0.393 2.922,0.961 -0.791,0.961 -1.341,0.411 -1.341,-0.874
  pour cut-out: 28.797,14.188 4.715,14.188 4.13,14.773 4.13,16.05 28.81,16.05
Int_1:
  pour cut-out: 29.027,14.279 5.069,14.279 5.069,16.511 29.027,16.478
  pour cut-out: 3.49,-0.859 3.49,0.411 2.934,0.967 -0.68,0.967 -1.341,0.306 -1.341,-0.874
Int_2:
  pour cut-out: 29.21,14.29 29.21,16.405 4.13,16.405 4.13,14.824 4.664,14.29
  pour cut-out: 28.89,-1.207 28.89,0.411 28.334,0.967 24.72,0.967 24.059,0.306 24.059,-1.223
Bot:
  pour cut-out: 8.48,10.16 8.592,10.272 9.18,10.272 9.18,9.598 9.198,9.581 9.173,9.556 8.463,9.556
  pour cut-out: 16.389,4.671 16.451,4.732 19.097,4.732 19.097,3.747 16.362,3.747
  pour cut-out: 19.57,5.507 19.595,5.532 20.27,5.532 20.27,4.945 20.288,4.928 20.263,4.903 19.553,4.903
  pour cut-out: 27.566,3.213 27.478,3.213 27.977,3.213 27.977,1.55 27.56,1.55
  pour cut-out: 25.345,4.263 25.37,4.288 26.045,4.288 26.045,3.701 26.063,3.684 26.038,3.659 25.328,3.659
  pour cut-out: 11.501,12.725 11.526,12.75 12.201,12.75 12.201,12.164 12.219,12.146 12.194,12.121 11.484,12.121
  pour cut-out: 9.698,13.226 9.723,13.251 10.398,13.251 10.398,12.664 10.416,12.647 10.391,12.622 9.681,12.622
  pour cut-out: 10.907,2.618 10.932,2.643 11.607,2.643 11.607,2.056 11.625,2.039 11.6,2.014 10.89,2.014
  pour cut-out: 8.403,2.618 8.428,2.643 9.103,2.643 9.103,2.056 9.12,2.039 9.095,2.014 8.385,2.014
  pour cut-out: 7.698,7.532 7.723,7.557 8.398,7.557 8.398,6.971 8.415,6.953 8.39,6.928 7.68,6.928
  pour cut-out: 8.403,4.978 8.428,5.003 9.103,5.003 9.103,4.416 9.103,4.328 9.103,3.85 8.37,3.85
  pour cut-out: 6.197,4.872 6.197,4.072 7.215,4.072 7.215,4.872
  pour cut-out: 22.074,3.916 20.197,3.916 20.197,0.937 24.408,0.937
  pour cut-out: 23.837,5.15 23.192,5.15 23.192,2.567 23.837,2.567
  pour cut-out: 6.915,10.591 6.94,10.616 7.615,10.616 7.615,10.029 7.633,10.012 7.608,9.987 6.898,9.987
  pour cut-out: 1.264,7.605 1.289,7.63 1.964,7.63 1.964,7.043 1.982,7.026 1.957,7.001 1.247,7.001
  pour cut-out: 5.181,2.928 5.206,2.953 5.881,2.953 5.881,2.366 5.899,2.349 5.874,2.324 5.164,2.324
  pour cut-out: 0.961,16.176 0.961,12.533 -3.355,12.533 -3.355,15.04 -2.219,16.176
  pour cut-out: 29.027,14.36 4.594,14.36 4.13,14.824 4.13,16.512 29.027,16.478
  pour cut-out: 28.998,-1.003 28.998,0.937 9.754,0.937 9.21,0.393 9.21,-1.033
  pour cut-out: 3.49,-0.863 3.49,-0.576 3.49,0.411 2.934,0.967 -0.68,0.967 -1.341,0.306 -1.341,-0.863

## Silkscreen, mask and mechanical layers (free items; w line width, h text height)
Top Overlay:
  text "14" at 15.923,14.024 h1.5
  text "11" at 23.454,14.02 h1.5
  text "10" at 26.089,14.023 h1.5
  text "16" at 10.796,13.989 h1.5
  text "15" at 13.346,13.994 h1.5
  text "13" at 18.407,13.981 h1.5
  text "12" at 20.899,13.973 h1.5
  text "9" at 28.51,13.969 h1.5
  text "VIN" at -0.883,13.582 h1.5
  text "GND" at 1.402,13.582 h1.5
  text "RST" at 4.187,13.582 h1.5
  text "+3V3" at 6.37,13.582 h1.5
  text "EVU-LI-2.1" at 21.84,12.649 h1.5 r270
  text "TX0" at -0.975,0.94 h1.5
  text "RX0" at 1.629,0.941 h1.5
  text "3" at 15.799,0.719 h1.5
  text "4" at 18.311,0.719 h1.5
  text "5" at 20.885,0.726 h1.5
  text "6" at 23.412,0.719 h1.5
  text "7" at 25.956,0.721 h1.5
  text "8" at 28.231,0.719 h1.5
  text "GND" at 5.266,0.708 h1.4
  text "GND" at 7.827,0.708 h1.4
  text "1" at 10.741,0.716 h1.5
  text "2" at 13.259,0.712 h1.5
Bottom Overlay:
  text "EVU-LI-2.1" at 21.738,5.375 h1.4 r270
Dimensions:
  lines w0.1: -3.81,-1.27 29.21,-1.27 29.21,16.51 -3.81,16.51 -3.81,-1.27
  lines w0.254: 29.474,-9.853 59.049,-9.853 59.049,-4.423 29.474,-4.423 29.474,-9.853
  text "ProjectName: EVU-LI-2.0" at 30.224,-6.437 h2.5
  text "TimeStamp: .ModifiedDate .ModifiedTime" at 30.224,-8.814 h2.5
Mechanical 2:
  the board outline again, w0.1
Mechanical 13:
  text "b" at -3.35,1.02 h1.6

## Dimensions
-3.81,-1.27 to -3.81,16.51 on Dimensions
29.21,16.51 to -3.81,16.51 on Dimensions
